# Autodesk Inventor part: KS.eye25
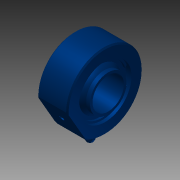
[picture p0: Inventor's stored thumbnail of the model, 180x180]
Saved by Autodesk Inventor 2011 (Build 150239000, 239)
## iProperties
Created: 2010-10
Part Number: KS.eye25
Document SubType Name: Modeling
Designer: tribel
Density: 1 g/cm^3
Author: tribel
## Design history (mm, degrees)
derived "Klinkby.KS øye.25.iam"
body "Solid1"
sketch "K-WS25N6.ipt:1"
sketch "K-WS25N1.ipt:1"
sketch "K-WS25N4.ipt:1"
sketch "K-WS25N4.ipt:2"
sketch "KS.øye.25.ipt:1"
sketch "KS.25.kule.ipt:1"
